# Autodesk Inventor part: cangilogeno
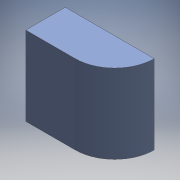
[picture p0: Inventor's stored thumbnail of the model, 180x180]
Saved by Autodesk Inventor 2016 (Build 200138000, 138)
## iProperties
Created: 2016-06
Part Number: cangilogeno
Material: Genérico
Document SubType Name: Modeling
Designer: adm
Density: 1 g/cm^3
Appearance: Valor por defecto
Author: adm
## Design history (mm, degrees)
sketch "Boceto1"
  geometry: L1 (22.5, 10)-(-22.5, 10); L2 (-22.5, 10)-(-22.5, -10); L3 (-22.5, -10)-(2.5, -10); L4 (22.5, 10)-(22.5, 10); L5 (22.5, 10)-(-22.5, -10); L6 (-22.5, 10)-(22.5, -10); A1 r 20 centre (2.5, 10) between (2.5, -10) and (22.5, 10); 1 further point
  constraints: 12 end point, 2 midpoint, 2 parallel, 2 point on circle, 2 point on line, 2 tangent, 1 centre point, 1 horizontal, 1 perpendicular
  dimensions: "d0" = 45 distance of L6.end L2.end; "d1" = 20 distance of L2.end L1.end; "d2" = 20 radius of A1
extrude "Extrusión1" new body sketch "Boceto1" distance "d3" = 40; taper "d4" = 0 deg
feature "Vaciado1" dims "d5" = 3
node "Sólido1"
